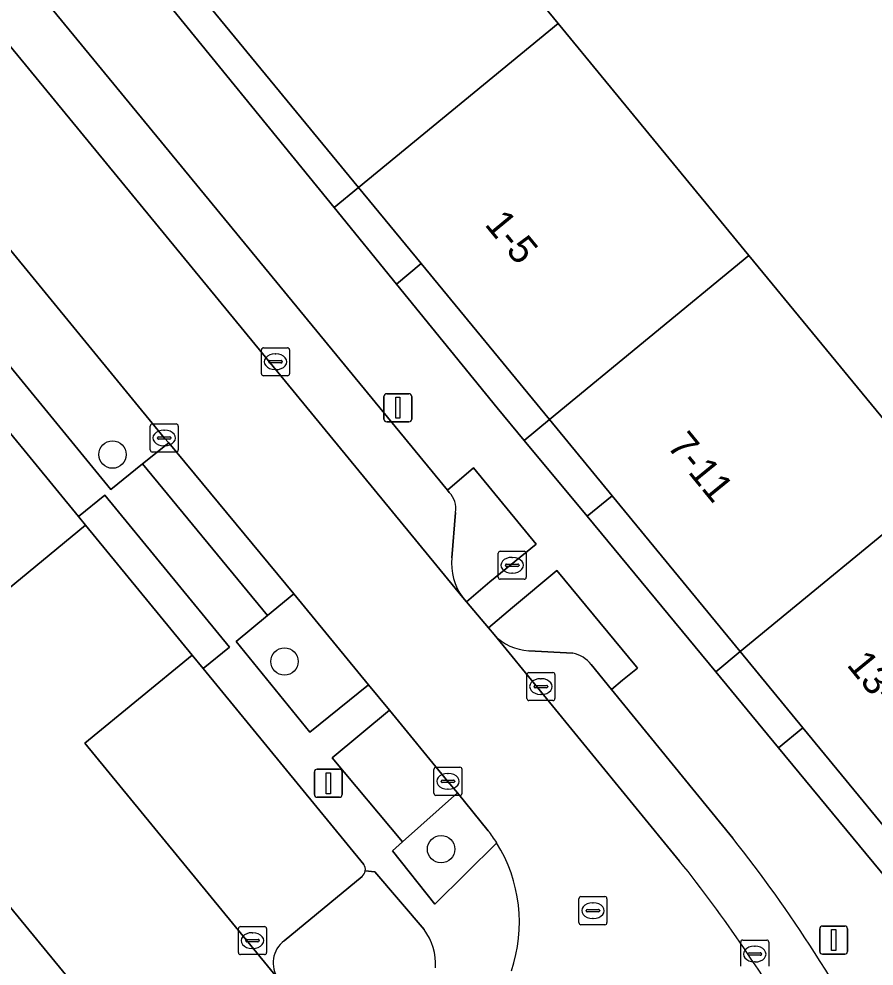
# Model space of a CAD drawing. Extents: x 162344 to 162869, y 381217 to 381818.
# Drawn here: x 162428.6 to 162459.05, y 381681.15 to 381714.88 of the extents above; entities that cross this region are included whole.
import ezdxf

# ---------------------------------------------------------------- set-up
doc = ezdxf.new("R2010")
doc.units = 0
for name, color, linetype in [('IMGEO_Berm_groen', 7, 'Continuous'), ('IMGEO_Boom', 7, 'Continuous'), ('IMGEO_Groenvoorziening', 7, 'Continuous'), ('IMGEO_Kolk', 7, 'Continuous'), ('IMGEO_Lichtmast', 7, 'Continuous'), ('IMGEO_Pand', 7, 'Continuous'), ('IMGEO_Pand_nummerreeks', 7, 'Continuous'), ('IMGEO_Parkeervlak_open', 7, 'Continuous'), ('IMGEO_Rijbaan_lokaal_open', 7, 'Continuous'), ('IMGEO_Rioolput', 7, 'Continuous'), ('IMGEO_Voetpad_open', 7, 'Continuous')]:
    doc.layers.add(name, color=color, linetype=linetype)

msp = doc.modelspace()

# ---------------------------------------------------------------- linework, layer by layer
at = {"layer": 'IMGEO_Berm_groen'}
msp.add_lwpolyline([(162419.664, 381712.99), (162426.56, 381704.589), (162431.873, 381698.117), (162433, 381699.03), (162433.929, 381699.783), (162433.769, 381699.955), (162423.612, 381712.341)], dxfattribs=at)
at = {"layer": 'IMGEO_Boom'}
for centre in [(162431.928, 381699.364), (162438.052, 381691.997), (162443.63, 381685.316)]:
    msp.add_circle(centre, 0.489, dxfattribs=at)
at = {"layer": 'IMGEO_Groenvoorziening'}
for points in [[(162471.549, 381716.061), (162469.643, 381714.467), (162467.863, 381716.602), (162469.783, 381718.202), (162463.314, 381726.102), (162461.333, 381724.518), (162459.563, 381726.678), (162461.541, 381728.274), (162451.996, 381739.827), (162449.119, 381737.441), (162434.479, 381725.379), (162437.492, 381721.752), (162438.041, 381722.212), (162438.864, 381721.224), (162441.001, 381722.982), (162447.798, 381714.718), (162454.595, 381706.454), (162461.391, 381698.19), (162468.188, 381689.926), (162474.743, 381681.955)], [(162444.402, 381694.279), (162444.534, 381694.123), (162445.364, 381694.832), (162447.02, 381696.173), (162444.783, 381698.896), (162443.858, 381698.099)], [(162443.858, 381698.099), (162443.923, 381698.02)], [(162444.146, 381697.307), (162444.014, 381695.693)], [(162448.974, 381691.885), (162449.697, 381691), (162450.093, 381691.327), (162450.623, 381691.763), (162450.589, 381691.804), (162447.758, 381695.241), (162446.171, 381693.919), (162445.318, 381693.193)], [(162445.318, 381693.193), (162445.52, 381692.954)], [(162446.755, 381692.381), (162448.317, 381692.29)], [(162444.211, 381687.318), (162442.251, 381685.574), (162441.894, 381685.257), (162443.409, 381683.352), (162445.61, 381685.541)], [(162445.31, 381685.972), (162444.211, 381687.318)], [(162440.814, 381684.344), (162438.042, 381682.05)], [(162443.027, 381682.456), (162441.272, 381684.508), (162440.932, 381684.549)]]:
    msp.add_lwpolyline(points, dxfattribs=at)
for points in [[(162433.897, 381717.139), (162433.063, 381716.452), (162439.822, 381708.158), (162440.694, 381708.875)], [(162442.924, 381706.164), (162442.04, 381705.437), (162445.632, 381701.029), (162446.59, 381699.87), (162447.491, 381700.611)], [(162449.721, 381697.9), (162448.828, 381697.166), (162453.41, 381691.626), (162454.287, 381692.347)], [(162438.382, 381694.405), (162437.451, 381693.636), (162436.333, 381692.713), (162438.954, 381689.478), (162441.043, 381691.171)], [(162441.792, 381690.262), (162439.756, 381688.562), (162442.251, 381685.574), (162444.211, 381687.318), (162443.875, 381687.73)], [(162456.517, 381689.636), (162455.647, 381688.921), (162460.23, 381683.381), (162461.084, 381684.083)]]:
    msp.add_lwpolyline(points, close=True, dxfattribs=at)
for centre, radius, start, end in [((162443.309, 381697.436), 0.847, 351.2096, 43.5259), ((162446.054, 381695.492), 2.05, 174.3845, 216.304), ((162446.83, 381694.161), 1.781, 222.6422, 267.5783), ((162448.155, 381691.291), 1.012, 35.9307, 80.7668), ((162440.827, 381682.532), 5.651, 32.1769, 37.5032), ((162440.62, 381684.592), 0.315, 307.9986, 352.1511), ((162441.325, 381681.212), 2.108, 356.7466, 36.1734), ((162438.626, 381681.266), 0.978, 126.6965, 215.5758)]:
    msp.add_arc(centre, radius, start, end, dxfattribs=at)
at = {"layer": 'IMGEO_Kolk'}
for p, q in [((162437.232, 381702.243), (162437.232, 381703.095)), ((162437.307, 381703.169), (162438.159, 381703.169)), ((162437.72, 381702.949), (162437.745, 381702.949)), ((162438.233, 381703.095), (162438.233, 381702.243)), ((162437.491, 381702.663), (162437.491, 381702.675)), ((162437.929, 381702.626), (162437.531, 381702.626)), ((162437.534, 381702.712), (162437.932, 381702.712)), ((162437.975, 381702.675), (162437.975, 381702.663)), ((162438.159, 381702.169), (162437.307, 381702.169)), ((162437.743, 381702.389), (162437.718, 381702.389)), ((162433.268, 381699.529), (162433.268, 381700.381)), ((162433.343, 381700.455), (162434.195, 381700.455)), ((162433.756, 381700.235), (162433.781, 381700.235)), ((162434.269, 381700.381), (162434.269, 381699.529)), ((162433.527, 381699.949), (162433.527, 381699.961)), ((162433.965, 381699.912), (162433.567, 381699.912)), ((162433.57, 381699.998), (162433.968, 381699.998)), ((162434.011, 381699.961), (162434.011, 381699.949)), ((162433.779, 381699.675), (162433.754, 381699.675)), ((162434.195, 381699.455), (162433.343, 381699.455)), ((162446.685, 381690.679), (162446.685, 381691.531)), ((162446.76, 381691.605), (162447.612, 381691.605)), ((162447.173, 381691.385), (162447.198, 381691.385)), ((162447.686, 381691.531), (162447.686, 381690.679)), ((162446.944, 381691.099), (162446.944, 381691.111)), ((162447.382, 381691.062), (162446.984, 381691.062)), ((162446.987, 381691.148), (162447.385, 381691.148)), ((162447.428, 381691.111), (162447.428, 381691.099)), ((162447.196, 381690.825), (162447.171, 381690.825)), ((162447.612, 381690.605), (162446.76, 381690.605)), ((162443.374, 381687.304), (162443.374, 381688.156)), ((162443.449, 381688.23), (162444.301, 381688.23)), ((162443.862, 381688.01), (162443.887, 381688.01)), ((162444.375, 381688.156), (162444.375, 381687.304)), ((162443.633, 381687.724), (162443.633, 381687.736)), ((162444.071, 381687.687), (162443.673, 381687.687)), ((162443.676, 381687.773), (162444.074, 381687.773)), ((162444.117, 381687.736), (162444.117, 381687.724)), ((162443.885, 381687.45), (162443.86, 381687.45)), ((162444.301, 381687.23), (162443.449, 381687.23)), ((162436.412, 381681.634), (162436.412, 381682.486)), ((162436.487, 381682.56), (162437.339, 381682.56)), ((162436.9, 381682.34), (162436.925, 381682.34)), ((162437.413, 381682.486), (162437.413, 381681.634)), ((162436.671, 381682.054), (162436.671, 381682.066)), ((162437.109, 381682.017), (162436.711, 381682.017)), ((162436.714, 381682.103), (162437.112, 381682.103)), ((162437.155, 381682.066), (162437.155, 381682.054)), ((162454.301, 381681.153), (162454.301, 381682.005)), ((162454.376, 381682.079), (162455.228, 381682.079)), ((162455.302, 381682.005), (162455.302, 381681.153)), ((162436.923, 381681.78), (162436.898, 381681.78)), ((162454.603, 381681.622), (162455.001, 381681.622)), ((162454.789, 381681.859), (162454.814, 381681.859)), ((162437.339, 381681.56), (162436.487, 381681.56)), ((162454.56, 381681.573), (162454.56, 381681.585)), ((162454.998, 381681.536), (162454.6, 381681.536)), ((162454.812, 381681.299), (162454.787, 381681.299)), ((162455.044, 381681.585), (162455.044, 381681.573))]:
    msp.add_line(p, q, dxfattribs=at)
for points in [[(162437.232, 381702.243), (162437.232, 381703.095)], [(162437.307, 381703.169), (162438.159, 381703.169)], [(162438.233, 381703.095), (162438.233, 381702.243)], [(162438.159, 381702.169), (162437.307, 381702.169)], [(162433.268, 381699.529), (162433.268, 381700.381)], [(162433.343, 381700.455), (162434.195, 381700.455)], [(162434.269, 381700.381), (162434.269, 381699.529)], [(162434.195, 381699.455), (162433.343, 381699.455)], [(162446.685, 381690.679), (162446.685, 381691.531)], [(162446.76, 381691.605), (162447.612, 381691.605)], [(162447.686, 381691.531), (162447.686, 381690.679)], [(162447.612, 381690.605), (162446.76, 381690.605)], [(162443.374, 381687.304), (162443.374, 381688.156)], [(162443.449, 381688.23), (162444.301, 381688.23)], [(162444.375, 381688.156), (162444.375, 381687.304)], [(162444.301, 381687.23), (162443.449, 381687.23)], [(162436.412, 381681.634), (162436.412, 381682.486)], [(162436.487, 381682.56), (162437.339, 381682.56)], [(162437.413, 381682.486), (162437.413, 381681.634)], [(162454.301, 381681.153), (162454.301, 381682.005)], [(162454.376, 381682.079), (162455.228, 381682.079)], [(162455.302, 381682.005), (162455.302, 381681.153)], [(162437.339, 381681.56), (162436.487, 381681.56)]]:
    msp.add_lwpolyline(points, dxfattribs=at)
for centre, radius, start, end in [((162437.309, 381703.093), 0.0765, 91.552, 178.448), ((162437.309, 381703.093), 0.0765, 91.552, 178.448), ((162438.157, 381703.093), 0.0765, 1.552, 88.448), ((162438.157, 381703.093), 0.0765, 1.552, 88.448), ((162437.531, 381702.672), 0.0403, 85.8775, 175.7526), ((162437.528, 381702.662), 0.0366, 178.938, 274.7102), ((162437.932, 381702.669), 0.043, 264.8664, 352.4533), ((162437.936, 381702.674), 0.0386, 1.7309, 96.639), ((162437.309, 381702.245), 0.0765, 181.552, 268.448), ((162437.309, 381702.245), 0.0765, 181.552, 268.448), ((162438.157, 381702.245), 0.0765, 271.552, 358.448), ((162438.157, 381702.245), 0.0765, 271.552, 358.448), ((162433.345, 381700.379), 0.0765, 91.552, 178.448), ((162433.345, 381700.379), 0.0765, 91.552, 178.448), ((162434.193, 381700.379), 0.0765, 1.552, 88.448), ((162434.193, 381700.379), 0.0765, 1.552, 88.448), ((162433.567, 381699.958), 0.0403, 85.8775, 175.7526), ((162433.564, 381699.948), 0.0366, 178.938, 274.7102), ((162433.968, 381699.955), 0.043, 264.8664, 352.4533), ((162433.972, 381699.96), 0.0386, 1.7309, 96.639), ((162433.345, 381699.531), 0.0765, 181.552, 268.448), ((162433.345, 381699.531), 0.0765, 181.552, 268.448), ((162434.193, 381699.531), 0.0765, 271.552, 358.448), ((162434.193, 381699.531), 0.0765, 271.552, 358.448), ((162446.762, 381691.529), 0.0765, 91.552, 178.448), ((162446.762, 381691.529), 0.0765, 91.552, 178.448), ((162447.61, 381691.529), 0.0765, 1.552, 88.448), ((162447.61, 381691.529), 0.0765, 1.552, 88.448), ((162446.984, 381691.108), 0.0403, 85.8775, 175.7526), ((162446.981, 381691.098), 0.0366, 178.938, 274.7102), ((162447.385, 381691.105), 0.043, 264.8664, 352.4533), ((162447.389, 381691.11), 0.0386, 1.7309, 96.639), ((162446.762, 381690.681), 0.0765, 181.552, 268.448), ((162446.762, 381690.681), 0.0765, 181.552, 268.448), ((162447.61, 381690.681), 0.0765, 271.552, 358.448), ((162447.61, 381690.681), 0.0765, 271.552, 358.448), ((162443.451, 381688.154), 0.0765, 91.552, 178.448), ((162443.451, 381688.154), 0.0765, 91.552, 178.448), ((162444.299, 381688.154), 0.0765, 1.552, 88.448), ((162444.299, 381688.154), 0.0765, 1.552, 88.448), ((162443.673, 381687.733), 0.0403, 85.8775, 175.7526), ((162443.67, 381687.723), 0.0366, 178.938, 274.7102), ((162444.074, 381687.73), 0.043, 264.8664, 352.4533), ((162444.078, 381687.735), 0.0386, 1.7309, 96.639), ((162443.451, 381687.306), 0.0765, 181.552, 268.448), ((162443.451, 381687.306), 0.0765, 181.552, 268.448), ((162444.299, 381687.306), 0.0765, 271.552, 358.448), ((162444.299, 381687.306), 0.0765, 271.552, 358.448), ((162436.489, 381682.484), 0.0765, 91.552, 178.448), ((162436.489, 381682.484), 0.0765, 91.552, 178.448), ((162437.337, 381682.484), 0.0765, 1.552, 88.448), ((162437.337, 381682.484), 0.0765, 1.552, 88.448), ((162436.711, 381682.063), 0.0403, 85.8775, 175.7526), ((162436.708, 381682.053), 0.0366, 178.938, 274.7102), ((162437.112, 381682.06), 0.043, 264.8664, 352.4533), ((162437.116, 381682.065), 0.0386, 1.7309, 96.639), ((162454.378, 381682.003), 0.0765, 91.552, 178.448), ((162454.378, 381682.003), 0.0765, 91.552, 178.448), ((162455.226, 381682.003), 0.0765, 1.552, 88.448), ((162455.226, 381682.003), 0.0765, 1.552, 88.448), ((162436.489, 381681.636), 0.0765, 181.552, 268.448), ((162436.489, 381681.636), 0.0765, 181.552, 268.448), ((162437.337, 381681.636), 0.0765, 271.552, 358.448), ((162437.337, 381681.636), 0.0765, 271.552, 358.448), ((162454.6, 381681.582), 0.0403, 85.8775, 175.7526), ((162455.005, 381681.584), 0.0386, 1.7309, 96.639), ((162454.597, 381681.572), 0.0366, 178.938, 274.7102), ((162455.001, 381681.579), 0.043, 264.8664, 352.4533)]:
    msp.add_arc(centre, radius, start, end, dxfattribs=at)
for centre, major_axis, ratio, start_param, end_param in [((162437.719, 381702.669), (-0.387, 0.002), 0.722429, 4.712389, 7.853982), ((162437.744, 381702.669), (-0.39, 0.002), 0.717154, 1.570796, 4.712389), ((162433.755, 381699.955), (-0.387, 0.002), 0.722429, 4.712389, 7.853982), ((162433.78, 381699.955), (-0.39, 0.002), 0.717154, 1.570796, 4.712389), ((162447.172, 381691.105), (-0.387, 0.002), 0.722429, 4.712389, 7.853982), ((162447.197, 381691.105), (-0.39, 0.002), 0.717154, 1.570796, 4.712389), ((162443.861, 381687.73), (-0.387, 0.002), 0.722429, 4.712389, 7.853982), ((162443.886, 381687.73), (-0.39, 0.002), 0.717154, 1.570796, 4.712389), ((162436.899, 381682.06), (-0.387, 0.002), 0.722429, 4.712389, 7.853982), ((162436.924, 381682.06), (-0.39, 0.002), 0.717154, 1.570796, 4.712389), ((162454.788, 381681.579), (-0.387, 0.002), 0.722429, 4.712389, 7.853982), ((162454.813, 381681.579), (-0.39, 0.002), 0.717154, 1.570796, 4.712389)]:
    msp.add_ellipse(centre, major_axis=major_axis, ratio=ratio, start_param=start_param, end_param=end_param, dxfattribs=at)
at = {"layer": 'IMGEO_Lichtmast'}
for p, q in [((162441.695, 381701.53), (162442.485, 381701.53)), ((162442.485, 381701.53), (162441.695, 381701.53)), ((162441.595, 381700.63), (162441.595, 381701.43)), ((162441.595, 381701.43), (162441.595, 381700.63)), ((162442.585, 381701.43), (162442.585, 381700.63)), ((162442.585, 381700.63), (162442.585, 381701.43)), ((162442.485, 381700.53), (162441.695, 381700.53)), ((162441.695, 381700.53), (162442.485, 381700.53)), ((162439.117, 381687.263), (162439.117, 381688.063)), ((162439.117, 381688.063), (162439.117, 381687.263)), ((162439.217, 381688.163), (162440.007, 381688.163)), ((162440.007, 381688.163), (162439.217, 381688.163)), ((162440.107, 381688.063), (162440.107, 381687.263)), ((162440.107, 381687.263), (162440.107, 381688.063)), ((162440.007, 381687.163), (162439.217, 381687.163)), ((162439.217, 381687.163), (162440.007, 381687.163)), ((162457.117, 381681.676), (162457.117, 381682.476)), ((162457.117, 381682.476), (162457.117, 381681.676)), ((162457.217, 381682.576), (162458.007, 381682.576)), ((162458.007, 381682.576), (162457.217, 381682.576)), ((162458.107, 381682.476), (162458.107, 381681.676)), ((162458.107, 381681.676), (162458.107, 381682.476)), ((162458.007, 381681.576), (162457.217, 381681.576)), ((162457.217, 381681.576), (162458.007, 381681.576))]:
    msp.add_line(p, q, dxfattribs=at)
for points in [[(162442.015, 381701.405), (162442.165, 381701.405), (162442.165, 381700.655), (162442.015, 381700.655), (162442.015, 381701.405)], [(162439.537, 381688.038), (162439.687, 381688.038), (162439.687, 381687.288), (162439.537, 381687.288), (162439.537, 381688.038)], [(162457.537, 381682.451), (162457.687, 381682.451), (162457.687, 381681.701), (162457.537, 381681.701), (162457.537, 381682.451)]]:
    msp.add_lwpolyline(points, dxfattribs=at)
for centre, start, end in [((162441.695, 381701.43), 90, 180), ((162441.695, 381701.43), 90, 180), ((162442.485, 381701.43), 0, 90), ((162442.485, 381701.43), 360, 90), ((162441.695, 381700.63), 180, 270), ((162441.695, 381700.63), 180, 270), ((162442.485, 381700.63), 270, 0), ((162442.485, 381700.63), 270, 0), ((162439.217, 381688.063), 90, 180), ((162439.217, 381688.063), 90, 180), ((162440.007, 381688.063), 0, 90), ((162440.007, 381688.063), 360, 90), ((162439.217, 381687.263), 180, 270), ((162439.217, 381687.263), 180, 270), ((162440.007, 381687.263), 270, 0), ((162440.007, 381687.263), 270, 0), ((162457.217, 381682.476), 90, 180), ((162457.217, 381682.476), 90, 180), ((162458.007, 381682.476), 0, 90), ((162458.007, 381682.476), 360, 90), ((162457.217, 381681.676), 180, 270), ((162457.217, 381681.676), 180, 270), ((162458.007, 381681.676), 270, 0), ((162458.007, 381681.676), 270, 0)]:
    msp.add_arc(centre, 0.1, start, end, dxfattribs=at)
at = {"layer": 'IMGEO_Pand'}
for points in [[(162447.798, 381714.718), (162441.001, 381722.982), (162438.864, 381721.224), (162433.897, 381717.139), (162440.694, 381708.875)], [(162447.798, 381714.718), (162440.694, 381708.875), (162442.924, 381706.164), (162447.491, 381700.611), (162454.595, 381706.454)], [(162454.595, 381706.454), (162447.491, 381700.611), (162449.721, 381697.9), (162454.287, 381692.347), (162461.391, 381698.19)], [(162461.391, 381698.19), (162454.287, 381692.347), (162456.517, 381689.636), (162461.084, 381684.083), (162468.188, 381689.926)]]:
    msp.add_lwpolyline(points, close=True, dxfattribs=at)
at = {"layer": 'IMGEO_Parkeervlak_open'}
for points in [[(162425.214, 381717.634), (162440.324, 381699.249), (162444.402, 381694.279)], [(162443.923, 381698.02), (162443.858, 381698.099), (162428.688, 381716.567)], [(162413.686, 381710.091), (162427.141, 381693.71), (162430.965, 381696.851), (162430.713, 381697.159), (162418.27, 381712.325)], [(162431.239, 381672.964), (162434.507, 381675.673), (162409.377, 381706.246)], [(162444.014, 381695.693), (162444.146, 381697.307)], [(162445.52, 381692.954), (162452.127, 381684.891)], [(162435.155, 381691.745), (162434.763, 381692.223), (162430.941, 381689.084), (162437.831, 381680.697)], [(162448.317, 381692.29), (162446.755, 381692.381)], [(162440.877, 381684.77), (162435.155, 381691.745)], [(162449.697, 381691), (162448.974, 381691.885)], [(162454.017, 381685.708), (162449.697, 381691)], [(162438.042, 381682.05), (162440.814, 381684.344)]]:
    msp.add_lwpolyline(points, dxfattribs=at)
for centre, radius, start, end in [((162443.309, 381697.436), 0.847, 351.2096, 43.5259), ((162446.054, 381695.492), 2.05, 174.3845, 216.304), ((162446.83, 381694.161), 1.781, 222.6422, 267.5783), ((162448.155, 381691.291), 1.012, 35.9307, 80.7668), ((162415.813, 381655.28), 48.841, 32.6589, 38.5362), ((162440.618, 381684.588), 0.316, 352.8614, 35.0891), ((162411.785, 381652.7), 51.611, 30.0534, 38.5887), ((162440.62, 381684.592), 0.315, 307.9986, 352.1511), ((162438.626, 381681.266), 0.978, 126.6965, 215.5758), ((162416.044, 381655.409), 48.576, 25.5992, 32.6771)]:
    msp.add_arc(centre, radius, start, end, dxfattribs=at)
at = {"layer": 'IMGEO_Rijbaan_lokaal_open'}
for points in [[(162425.009, 381717.878), (162424.917, 381718.008), (162421.331, 381715.024), (162421.42, 381714.942), (162423.612, 381712.341), (162433.769, 381699.955), (162433.929, 381699.783), (162438.382, 381694.405), (162441.043, 381691.171), (162441.792, 381690.262), (162443.875, 381687.73), (162444.211, 381687.318), (162445.31, 381685.972)], [(162445.52, 381692.954), (162445.318, 381693.193), (162444.534, 381694.123), (162444.402, 381694.279), (162440.324, 381699.249), (162425.214, 381717.634)], [(162413.686, 381710.091), (162412.482, 381711.546), (162407.99, 381707.932), (162409.377, 381706.246), (162434.507, 381675.673), (162435.989, 381676.902), (162437.013, 381677.75), (162438.713, 381679.16)], [(162438.753, 381679.584), (162437.831, 381680.697), (162430.941, 381689.084), (162434.763, 381692.223), (162430.965, 381696.851), (162427.141, 381693.71), (162413.686, 381710.091)], [(162452.127, 381684.891), (162445.52, 381692.954)]]:
    msp.add_lwpolyline(points, dxfattribs=at)
for centre, radius, start, end in [((162440.827, 381682.532), 5.651, 32.1769, 37.5032), ((162441.078, 381682.713), 5.342, 341.1284, 31.9686), ((162411.785, 381652.7), 51.611, 30.0534, 38.5887)]:
    msp.add_arc(centre, radius, start, end, dxfattribs=at)
at = {"layer": 'IMGEO_Rioolput'}
for p, q in [((162445.663, 381694.998), (162445.663, 381695.85)), ((162445.738, 381695.924), (162446.59, 381695.924)), ((162446.664, 381695.85), (162446.664, 381694.998)), ((162445.922, 381695.418), (162445.922, 381695.43)), ((162445.965, 381695.467), (162446.363, 381695.467)), ((162446.151, 381695.704), (162446.176, 381695.704)), ((162446.406, 381695.43), (162446.406, 381695.418)), ((162446.36, 381695.381), (162445.962, 381695.381)), ((162446.174, 381695.144), (162446.149, 381695.144)), ((162446.59, 381694.924), (162445.738, 381694.924)), ((162448.613, 381683.625), (162449.465, 381683.625)), ((162448.538, 381682.699), (162448.538, 381683.551)), ((162449.026, 381683.405), (162449.051, 381683.405)), ((162449.539, 381683.551), (162449.539, 381682.699)), ((162448.797, 381683.119), (162448.797, 381683.131)), ((162449.235, 381683.082), (162448.837, 381683.082)), ((162448.84, 381683.168), (162449.238, 381683.168)), ((162449.281, 381683.131), (162449.281, 381683.119)), ((162449.465, 381682.625), (162448.613, 381682.625)), ((162449.049, 381682.845), (162449.024, 381682.845))]:
    msp.add_line(p, q, dxfattribs=at)
for points in [[(162445.663, 381694.998), (162445.663, 381695.85)], [(162445.738, 381695.924), (162446.59, 381695.924)], [(162446.664, 381695.85), (162446.664, 381694.998)], [(162446.59, 381694.924), (162445.738, 381694.924)], [(162448.613, 381683.625), (162449.465, 381683.625)], [(162448.538, 381682.699), (162448.538, 381683.551)], [(162449.539, 381683.551), (162449.539, 381682.699)], [(162449.465, 381682.625), (162448.613, 381682.625)]]:
    msp.add_lwpolyline(points, dxfattribs=at)
for centre, radius, start, end in [((162445.74, 381695.848), 0.0765, 91.552, 178.448), ((162445.74, 381695.848), 0.0765, 91.552, 178.448), ((162446.588, 381695.848), 0.0765, 1.552, 88.448), ((162446.588, 381695.848), 0.0765, 1.552, 88.448), ((162445.962, 381695.427), 0.0403, 85.8775, 175.7526), ((162446.367, 381695.429), 0.0386, 1.7309, 96.639), ((162445.959, 381695.417), 0.0366, 178.938, 274.7102), ((162446.363, 381695.424), 0.043, 264.8664, 352.4533), ((162445.74, 381695), 0.0765, 181.552, 268.448), ((162445.74, 381695), 0.0765, 181.552, 268.448), ((162446.588, 381695), 0.0765, 271.552, 358.448), ((162446.588, 381695), 0.0765, 271.552, 358.448), ((162448.615, 381683.549), 0.0765, 91.552, 178.448), ((162448.615, 381683.549), 0.0765, 91.552, 178.448), ((162449.463, 381683.549), 0.0765, 1.552, 88.448), ((162449.463, 381683.549), 0.0765, 1.552, 88.448), ((162448.837, 381683.128), 0.0403, 85.8775, 175.7526), ((162448.834, 381683.118), 0.0366, 178.938, 274.7102), ((162449.238, 381683.125), 0.043, 264.8664, 352.4533), ((162449.242, 381683.13), 0.0386, 1.7309, 96.639), ((162448.615, 381682.701), 0.0765, 181.552, 268.448), ((162448.615, 381682.701), 0.0765, 181.552, 268.448), ((162449.463, 381682.701), 0.0765, 271.552, 358.448), ((162449.463, 381682.701), 0.0765, 271.552, 358.448)]:
    msp.add_arc(centre, radius, start, end, dxfattribs=at)
for centre, major_axis, ratio, start_param, end_param in [((162446.15, 381695.424), (-0.387, 0.002), 0.722429, 4.712389, 7.853982), ((162446.175, 381695.424), (-0.39, 0.002), 0.717154, 1.570796, 4.712389), ((162449.025, 381683.125), (-0.387, 0.002), 0.722429, 4.712389, 7.853982), ((162449.05, 381683.125), (-0.39, 0.002), 0.717154, 1.570796, 4.712389)]:
    msp.add_ellipse(centre, major_axis=major_axis, ratio=ratio, start_param=start_param, end_param=end_param, dxfattribs=at)
at = {"layer": 'IMGEO_Voetpad_open'}
for points in [[(162429.986, 381721.677), (162429.68, 381721.488), (162427.504, 381719.918), (162429.582, 381717.324), (162428.688, 381716.567), (162443.858, 381698.099), (162444.783, 381698.896), (162447.02, 381696.173), (162445.364, 381694.832), (162444.534, 381694.123), (162445.318, 381693.193), (162446.171, 381693.919), (162447.758, 381695.241), (162450.589, 381691.804), (162450.623, 381691.763), (162450.093, 381691.327), (162449.697, 381691), (162454.017, 381685.708)], [(162439.822, 381708.158), (162433.063, 381716.452), (162432.172, 381717.479), (162432.171, 381717.481), (162429.884, 381720.266)], [(162445.61, 381685.541), (162443.409, 381683.352), (162441.894, 381685.257), (162442.251, 381685.574), (162439.756, 381688.562), (162441.792, 381690.262), (162441.043, 381691.171), (162438.954, 381689.478), (162436.333, 381692.713), (162437.451, 381693.636), (162433, 381699.03), (162431.873, 381698.117), (162426.56, 381704.589), (162419.664, 381712.99)], [(162418.27, 381712.325), (162430.713, 381697.159), (162431.649, 381697.915), (162436.089, 381692.513), (162435.155, 381691.745), (162440.877, 381684.77)], [(162473.727, 381665.25), (162474.439, 381665.794), (162470.329, 381670.872), (162466.808, 381675.428), (162462.467, 381680.676), (162460.23, 381683.381), (162455.647, 381688.921), (162453.41, 381691.626), (162448.828, 381697.166), (162446.59, 381699.87), (162445.632, 381701.029), (162442.04, 381705.437), (162439.822, 381708.158)], [(162440.932, 381684.549), (162441.272, 381684.508), (162443.027, 381682.456)]]:
    msp.add_lwpolyline(points, dxfattribs=at)
for points in [[(162440.694, 381708.875), (162439.822, 381708.158), (162442.04, 381705.437), (162442.924, 381706.164)], [(162447.491, 381700.611), (162446.59, 381699.87), (162448.828, 381697.166), (162449.721, 381697.9)], [(162433.929, 381699.783), (162433, 381699.03), (162437.451, 381693.636), (162438.382, 381694.405)], [(162431.649, 381697.915), (162430.713, 381697.159), (162430.965, 381696.851), (162434.763, 381692.223), (162435.155, 381691.745), (162436.089, 381692.513)], [(162454.287, 381692.347), (162453.41, 381691.626), (162455.647, 381688.921), (162456.517, 381689.636)]]:
    msp.add_lwpolyline(points, close=True, dxfattribs=at)
for centre, radius, start, end in [((162415.813, 381655.28), 48.841, 32.6589, 38.5362), ((162441.078, 381682.713), 5.342, 341.1284, 31.9686), ((162440.618, 381684.588), 0.316, 352.8614, 35.0891), ((162441.325, 381681.212), 2.108, 356.7466, 36.1734), ((162416.044, 381655.409), 48.576, 25.5992, 32.6771)]:
    msp.add_arc(centre, radius, start, end, dxfattribs=at)

# ---------------------------------------------------------------- texts
at = {"layer": 'IMGEO_Pand_nummerreeks'}
for s, rotation, p in [('1-5', 309.5339, (162445.154, 381707.55)), ('7-11', 309.1729, (162451.648, 381699.658)), ('13-17', 309.3219, (162458.048, 381691.869))]:
    msp.add_text(s, height=1, rotation=rotation, dxfattribs=at).set_placement(p)

doc.saveas('drawing.dxf')
